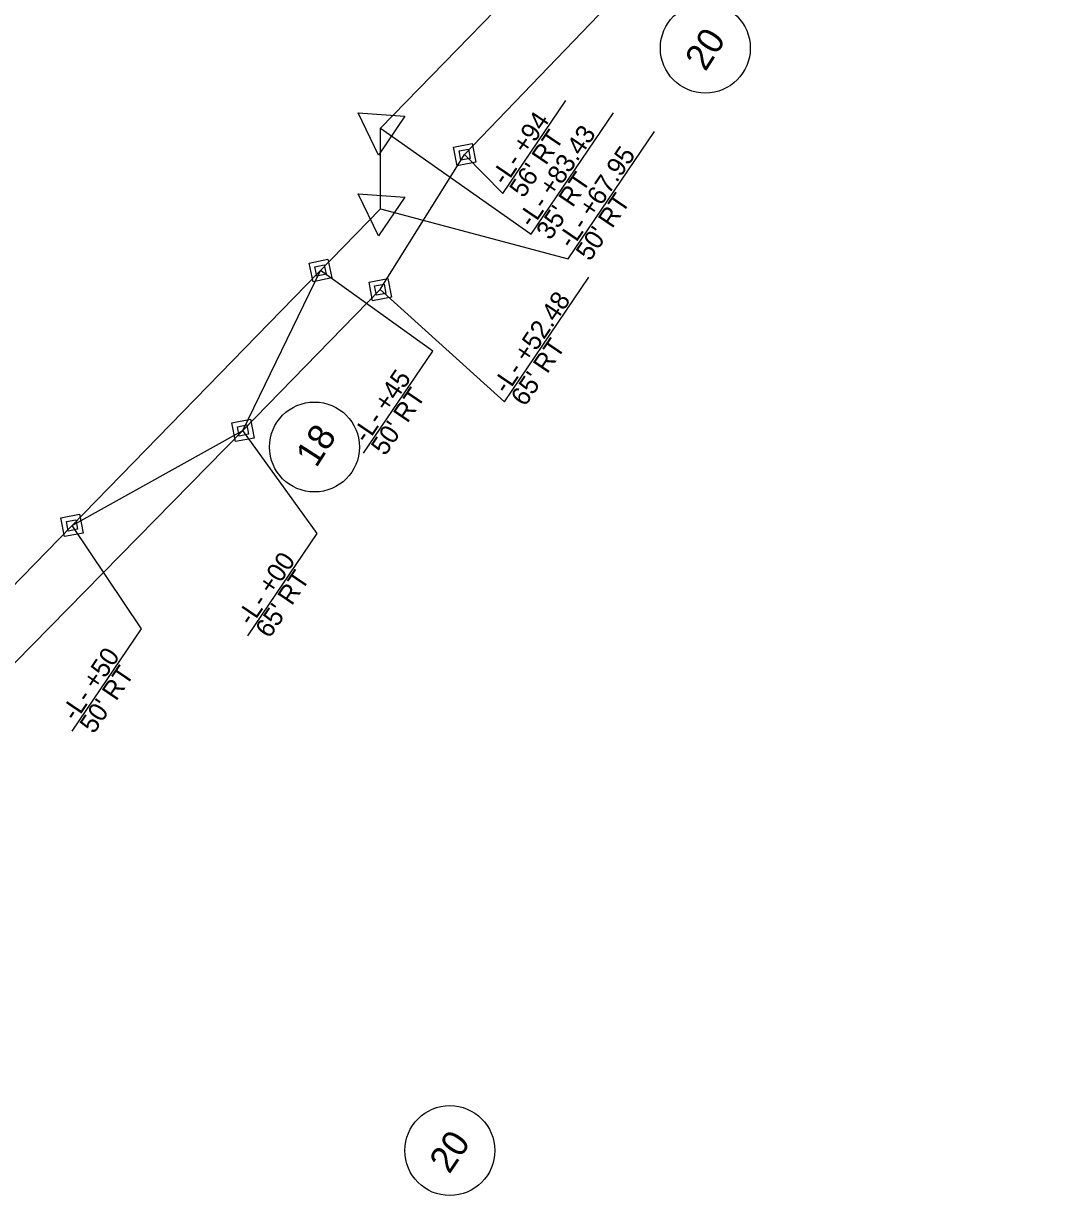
# Model space of a CAD drawing. Extents: x 1975689 to 1978251, y 778490 to 782347.
# Drawn here: x 1976741.7 to 1977014.8, y 779647 to 779959.7 of the extents above; entities that cross this region are included whole.
import ezdxf

# ---------------------------------------------------------------- set-up
doc = ezdxf.new("R2010")
doc.units = 0
for name, color, linetype in [('Prop Easement Permanent Drainage Utility', 7, 'Continuous'), ('Prop Easement Permanent Drainage Utility Station Offsets', 7, 'Continuous'), ('Prop Easement Permanent Utility', 7, 'Continuous'), ('Prop Easement Permanent Utility Station Offsets', 7, 'Continuous'), ('Prop Parcel Number CELL', 7, 'Continuous'), ('Prop ROW Marker CELL', 7, 'Continuous'), ('Prop ROW Permanent Easement CELL', 7, 'Continuous'), ('Prop ROW RW Lines', 7, 'Continuous'), ('Prop ROW Station Offsets', 7, 'Continuous')]:
    doc.layers.add(name, color=color, linetype=linetype)

msp = doc.modelspace()

# ---------------------------------------------------------------- linework, layer by layer
at = {"layer": 'Prop Easement Permanent Drainage Utility'}
for p, q in [((1976800.32, 779851.09), (1976820.98, 779893.79)), ((1976754.68, 779825.75), (1976800.32, 779851.09))]:
    msp.add_line(p, q, dxfattribs=at)
at = {"layer": 'Prop Easement Permanent Drainage Utility Station Offsets'}
for p, q in [((1976851, 779872.28), (1976820.98, 779893.79)), ((1976832.49, 779845), (1976851, 779872.28)), ((1976820.12, 779823.58), (1976800.32, 779851.09)), ((1976773.25, 779798.13), (1976754.68, 779825.75)), ((1976801.62, 779796.31), (1976820.12, 779823.58)), ((1976754.74, 779770.85), (1976773.25, 779798.13))]:
    msp.add_line(p, q, dxfattribs=at)
at = {"layer": 'Prop Easement Permanent Utility'}
for p, q in [((1976859.48, 779924.69), (1976952.28, 780021.36)), ((1976836.95, 779888.68), (1976859.48, 779924.69)), ((1976800.32, 779851.09), (1976836.95, 779888.68)), ((1976646.76, 779694.95), (1976800.32, 779851.09))]:
    msp.add_line(p, q, dxfattribs=at)
at = {"layer": 'Prop Easement Permanent Utility Station Offsets'}
for p, q in [((1976869.71, 779914.34), (1976886.52, 779939.11)), ((1976869.71, 779914.34), (1976859.48, 779924.69)), ((1976870.09, 779858.69), (1976892.67, 779891.97)), ((1976836.95, 779888.68), (1976870.09, 779858.69))]:
    msp.add_line(p, q, dxfattribs=at)
at = {"layer": 'Prop Parcel Number CELL'}
for p, q in [((1976923.72, 779953.11), (1976923.72, 779953.11)), ((1976819.39, 779846.68), (1976819.39, 779846.68)), ((1976855.53, 779658.96), (1976855.53, 779658.96))]:
    msp.add_line(p, q, dxfattribs=at)
for centre in [(1976923.72, 779953.11), (1976819.39, 779846.68), (1976855.53, 779658.96)]:
    msp.add_circle(centre, 12, dxfattribs=at)
at = {"layer": 'Prop ROW Marker CELL'}
for p, q in [((1976837.06, 779931.78), (1976837.06, 779931.78)), ((1976859.48, 779924.69), (1976859.48, 779924.69)), ((1976837, 779910.23), (1976837, 779910.23)), ((1976820.98, 779893.79), (1976820.98, 779893.79)), ((1976836.95, 779888.68), (1976836.95, 779888.68)), ((1976800.32, 779851.09), (1976800.32, 779851.09)), ((1976754.68, 779825.75), (1976754.68, 779825.75))]:
    msp.add_line(p, q, dxfattribs=at)
for points in [[(1976836.53, 779924.58), (1976831.1, 779935.82), (1976843.55, 779934.93)], [(1976836.47, 779903.03), (1976831.04, 779914.27), (1976843.49, 779913.38)]]:
    msp.add_lwpolyline(points, close=True, dxfattribs=at)
at = {"layer": 'Prop ROW Permanent Easement CELL'}
for points in [[(1976856.5, 779926.71), (1976861.5, 779927.67), (1976862.46, 779922.67), (1976857.46, 779921.71)], [(1976857.99, 779925.7), (1976860.49, 779926.18), (1976860.97, 779923.68), (1976858.47, 779923.2)], [(1976817.96, 779895.73), (1976822.93, 779896.82), (1976824.01, 779891.84), (1976819.04, 779890.76)], [(1976819.47, 779894.76), (1976821.96, 779895.3), (1976822.5, 779892.81), (1976820.01, 779892.27)], [(1976833.97, 779890.7), (1976838.97, 779891.65), (1976839.92, 779886.65), (1976834.93, 779885.7)], [(1976835.46, 779889.69), (1976837.96, 779890.16), (1976838.44, 779887.66), (1976835.94, 779887.19)], [(1976797.34, 779853.11), (1976802.34, 779854.07), (1976803.3, 779849.07), (1976798.3, 779848.11)], [(1976798.83, 779852.1), (1976801.33, 779852.58), (1976801.81, 779850.08), (1976799.31, 779849.6)], [(1976751.7, 779827.77), (1976756.7, 779828.73), (1976757.66, 779823.73), (1976752.66, 779822.77)], [(1976753.19, 779826.76), (1976755.69, 779827.24), (1976756.17, 779824.74), (1976753.67, 779824.26)]]:
    msp.add_lwpolyline(points, close=True, dxfattribs=at)
at = {"layer": 'Prop ROW RW Lines'}
for p, q in [((1976837.06, 779931.78), (1977014.81, 780114.17)), ((1976837, 779910.23), (1976837.06, 779931.78)), ((1976602.02, 779669.1), (1976837, 779910.23))]:
    msp.add_line(p, q, dxfattribs=at)
at = {"layer": 'Prop ROW Station Offsets'}
for p, q in [((1976877.26, 779903.51), (1976899.19, 779935.83)), ((1976837.06, 779931.78), (1976877.26, 779903.51)), ((1976887.16, 779896.92), (1976910.17, 779930.83)), ((1976837, 779910.23), (1976887.16, 779896.92))]:
    msp.add_line(p, q, dxfattribs=at)

# ---------------------------------------------------------------- texts
at = {"layer": 'Prop Easement Permanent Drainage Utility Station Offsets'}
for s, p in [('-L- +45', (1976833.39, 779847.4)), ("50' RT", (1976838.27, 779844.09)), ('-L- +00', (1976802.51, 779798.71)), ("65' RT", (1976807.39, 779795.4)), ('-L- +50', (1976755.64, 779773.25)), ("50' RT", (1976760.52, 779769.94))]:
    msp.add_text(s, height=5, rotation=55.8441, dxfattribs=at).set_placement(p)
at = {"layer": 'Prop Easement Permanent Utility Station Offsets'}
for s, p in [('-L- +94', (1976870.34, 779916.21)), ("56' RT", (1976875.21, 779912.9)), ('-L- +52.48', (1976870.72, 779860.56)), ("65' RT", (1976875.6, 779857.25))]:
    msp.add_text(s, height=5, rotation=55.8441, dxfattribs=at).set_placement(p)
at = {"layer": 'Prop Parcel Number CELL'}
for s, rotation, p in [('20', 57.2884, (1976923.75, 779946.65)), ('18', 57.2884, (1976819.87, 779840.93)), ('20', 55.8441, (1976855.4, 779652.5))]:
    msp.add_text(s, height=7, rotation=rotation, dxfattribs=at).set_placement(p)
at = {"layer": 'Prop ROW Station Offsets'}
for s, p in [('-L- +83.43', (1976877.49, 779904.93)), ('-L- +67.95', (1976888.06, 779899.32)), ("35' RT", (1976882.36, 779901.62)), ("50' RT", (1976892.94, 779896.01))]:
    msp.add_text(s, height=5, rotation=55.8441, dxfattribs=at).set_placement(p)

doc.saveas('drawing.dxf')
